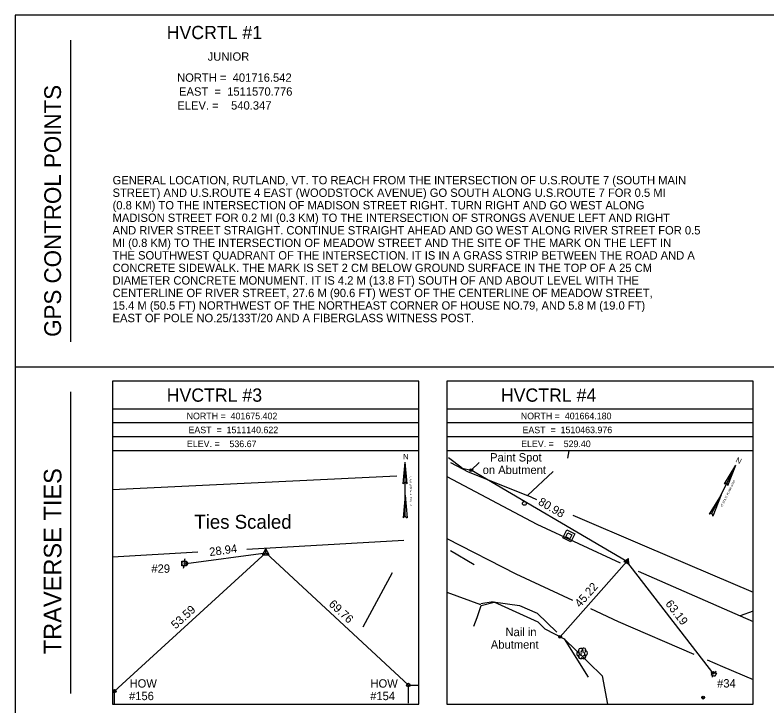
# Model space of a CAD drawing. Extents: x 1508412 to 1509054, y 401108 to 401963.
# Drawn here: x 1508413.7 to 1508683.7, y 401715.1 to 401963.2 of the extents above; entities that cross this region are included whole.
import ezdxf

# ---------------------------------------------------------------- set-up
doc = ezdxf.new("R2010")
doc.units = 0
for name, color, linetype in [('BSUBM', 7, 'Continuous'), ('CBP', 7, 'Continuous'), ('CPSM', 7, 'Continuous'), ('Default', 7, 'Continuous'), ('DS', 7, 'Continuous'), ('LAWA', 7, 'Continuous'), ('LBC', 7, 'Continuous'), ('Level 3', 7, 'Continuous'), ('Level 5', 7, 'Continuous'), ('LFNC', 7, 'Continuous'), ('LTD', 7, 'Continuous'), ('LWS', 7, 'Continuous'), ('NBL2', 7, 'Continuous'), ('NNA_P', 7, 'Continuous'), ('PET', 7, 'Continuous'), ('RDP', 7, 'Continuous'), ('RGR', 7, 'Continuous'), ('SSGN', 7, 'Continuous'), ('UP', 7, 'Continuous'), ('UPGW', 7, 'Continuous')]:
    doc.layers.add(name, color=color, linetype=linetype)

msp = doc.modelspace()

# ---------------------------------------------------------------- linework, layer by layer
at = {"layer": 'BSUBM'}
for p, q in [((1508574.2, 401800.46), (1508577.53, 401799.76)), ((1508577.53, 401799.76), (1508580.38, 401802.47)), ((1508603.93, 401742.74), (1508610.85, 401739.18)), ((1508610.85, 401739.18), (1508619.53, 401725.38))]:
    msp.add_line(p, q, dxfattribs=at)
for points in [[(1508574.2, 401800.46), (1508569.35, 401804.23)], [(1508601.58, 401745.15), (1508585.76, 401752.32)], [(1508601.58, 401745.15), (1508603.93, 401742.74)]]:
    msp.add_lwpolyline(points, dxfattribs=at)
at = {"layer": 'CBP'}
for centre, radius in [((1508577.53, 401799.76), 0.5), ((1508577.53, 401799.76), 0.0667), ((1508475.09, 401766.23), 0.625), ((1508475.09, 401766.23), 0.0833), ((1508609.46, 401739.9), 0.5), ((1508609.46, 401739.9), 0.0667), ((1508664.25, 401726.94), 0.5), ((1508664.25, 401726.94), 0.0667), ((1508554.92, 401722.59), 0.625), ((1508554.92, 401722.59), 0.0833), ((1508449.38, 401720.4), 0.625), ((1508449.38, 401720.4), 0.625), ((1508449.38, 401720.4), 0.0833), ((1508449.38, 401720.4), 0.0833)]:
    msp.add_circle(centre, radius, dxfattribs=at)
at = {"layer": 'CPSM'}
for p, q in [((1508502.5, 401769.29), (1508503.75, 401771.46)), ((1508505, 401769.29), (1508503.75, 401771.46)), ((1508503.75, 401770.02), (1508503.75, 401771.46)), ((1508502.5, 401769.29), (1508503.75, 401770.02)), ((1508502.5, 401769.29), (1508505, 401769.29)), ((1508503.75, 401770.02), (1508503.75, 401770.02)), ((1508503.75, 401770.02), (1508505, 401769.29)), ((1508632.27, 401766.93), (1508633.93, 401768.04)), ((1508633.42, 401767), (1508633.93, 401768.04)), ((1508634.06, 401766.04), (1508633.93, 401768.04)), ((1508632.27, 401766.93), (1508633.42, 401767)), ((1508632.27, 401766.93), (1508634.06, 401766.04)), ((1508633.42, 401767), (1508633.42, 401767)), ((1508633.42, 401767), (1508634.06, 401766.04))]:
    msp.add_line(p, q, dxfattribs=at)
at = {"layer": 'Default'}
for p, q in [((1508633.42, 401767), (1508577.53, 401799.76)), ((1508503.75, 401770.02), (1508449.38, 401720.4)), ((1508475.09, 401766.23), (1508503.75, 401770.02)), ((1508554.92, 401722.59), (1508503.75, 401770.02)), ((1508633.42, 401767), (1508609.46, 401739.9)), ((1508664.25, 401726.94), (1508633.42, 401767))]:
    msp.add_line(p, q, dxfattribs=at)
at = {"layer": 'DS'}
for p, q in [((1508610.43, 401775.44), (1508611.85, 401778.31)), ((1508611.85, 401778.31), (1508614.72, 401776.89)), ((1508611.5, 401775.8), (1508612.21, 401777.23)), ((1508612.94, 401775.09), (1508611.5, 401775.8)), ((1508612.21, 401777.23), (1508613.65, 401776.53)), ((1508612.58, 401776.16), (1508612.58, 401776.16)), ((1508612.58, 401776.16), (1508612.58, 401776.16)), ((1508613.65, 401776.53), (1508612.94, 401775.09)), ((1508614.72, 401776.89), (1508613.3, 401774.02)), ((1508613.3, 401774.02), (1508610.43, 401775.44))]:
    msp.add_line(p, q, dxfattribs=at)
at = {"layer": 'LAWA'}
for points in [[(1508612.19, 401804.06), (1508612.65, 401806.71)], [(1508570.07, 401802.5), (1508576.44, 401799.14)], [(1508576.44, 401799.14), (1508597.68, 401790.66)], [(1508597.68, 401790.66), (1508606.93, 401799.21)], [(1508549.06, 401762.88), (1508538.62, 401743.39)], [(1508568.69, 401755.89), (1508580.89, 401751.55)], [(1508585.42, 401752.42), (1508581.01, 401751.72)], [(1508585.42, 401752.42), (1508594.85, 401751.13)], [(1508594.85, 401751.13), (1508601.19, 401748.35), (1508608.27, 401741.58)], [(1508611.32, 401738.67), (1508614.67, 401735.47), (1508624.56, 401725.85), (1508626.4, 401715.71)]]:
    msp.add_lwpolyline(points, dxfattribs=at)
at = {"layer": 'LBC'}
for points in [[(1508554.92, 401716.01), (1508554.92, 401722.59), (1508558.42, 401722.59)], [(1508449.38, 401715.71), (1508449.38, 401720.4), (1508448.69, 401720.4)]]:
    msp.add_lwpolyline(points, dxfattribs=at)
at = {"layer": 'LFNC'}
for points in [[(1508601.1, 401789.1), (1508597.68, 401790.66)], [(1508613.97, 401783.53), (1508639.76, 401772.58), (1508678.69, 401755.98)]]:
    msp.add_lwpolyline(points, dxfattribs=at)
at = {"layer": 'LTD'}
msp.add_line((1508617.33, 401733.99), (1508617.33, 401733.99), dxfattribs=at)
msp.add_line((1508617.33, 401733.99), (1508617.33, 401733.99), dxfattribs=at)
msp.add_arc((1508617.87, 401735.01), 0.838, 309.2777, 154.7068, dxfattribs=at)
for centre, major_axis, ratio, start_param, end_param in [((1508617, 401734.75), (0.687, -0.795), 0.895232, 1.570796, 4.712389), ((1508616.3, 401733.87), (0.05, -0.954), 0.959034, 3.141593, 6.283185), ((1508616.8, 401732.92), (0.565, 0.667), 0.942809, 1.570796, 4.712389), ((1508616.74, 401733.62), (-0.478, 0.161), 0.423636, 0, 3.141593), ((1508617.35, 401734.4), (-0.43, -0.494), 0.645439, 3.141593, 6.283185), ((1508617.76, 401733.04), (-0.501, 0.954), 0.841452, 1.570796, 4.712389), ((1508617.63, 401733.7), (-0.123, 0.655), 0.989748, 3.141593, 6.283185), ((1508618.29, 401734.04), (-0.989, 0.057), 0.949671, 1.570796, 4.712389)]:
    msp.add_ellipse(centre, major_axis=major_axis, ratio=ratio, start_param=start_param, end_param=end_param, dxfattribs=at)
at = {"layer": 'LWS'}
msp.add_lwpolyline([(1508578.46, 401743.72), (1508579.67, 401746.83), (1508581.03, 401751.18), (1508585.76, 401752.32)], dxfattribs=at)
at = {"layer": 'NBL2'}
for p, q in [((1508433.7, 401845.87), (1508433.7, 401954.21)), ((1508413.7, 401836.87), (1509053.7, 401836.87)), ((1508433.7, 401719.54), (1508433.7, 401827.87)), ((1508558.69, 401821.71), (1508448.69, 401821.71)), ((1508678.69, 401821.71), (1508568.69, 401821.71)), ((1508558.69, 401816.71), (1508448.69, 401816.71)), ((1508678.69, 401816.71), (1508568.69, 401816.71)), ((1508558.69, 401811.71), (1508448.69, 401811.71)), ((1508678.69, 401811.71), (1508568.69, 401811.71)), ((1508558.69, 401806.71), (1508448.69, 401806.71)), ((1508678.69, 401806.71), (1508568.69, 401806.71))]:
    msp.add_line(p, q, dxfattribs=at)
for points in [[(1508413.7, 401543.21), (1509053.7, 401543.21), (1509053.7, 401963.21), (1508413.7, 401963.21)], [(1508448.69, 401715.71), (1508558.69, 401715.71), (1508558.69, 401831.71), (1508448.69, 401831.71)], [(1508568.69, 401715.71), (1508678.69, 401715.71), (1508678.69, 401831.71), (1508568.69, 401831.71)]]:
    msp.add_lwpolyline(points, close=True, dxfattribs=at)
at = {"layer": 'NNA_P'}
for p, q in [((1508553.11, 401794.8), (1508553.81, 401802.59)), ((1508553.81, 401783.22), (1508553.81, 401802.59)), ((1508554.5, 401794.8), (1508553.81, 401802.59)), ((1508663.91, 401784.15), (1508672.47, 401801.52)), ((1508668.41, 401794.84), (1508672.47, 401801.52)), ((1508669.65, 401794.23), (1508672.47, 401801.52)), ((1508553.11, 401794.8), (1508553.81, 401795.56)), ((1508554.5, 401794.8), (1508553.81, 401795.56)), ((1508668.41, 401794.84), (1508669.37, 401795.22)), ((1508669.65, 401794.23), (1508669.37, 401795.22)), ((1508553.81, 401790.74), (1508553.09, 401782.58)), ((1508553.81, 401790.74), (1508554.53, 401782.58)), ((1508667.24, 401790.9), (1508662.98, 401783.89)), ((1508667.24, 401790.9), (1508664.27, 401783.26)), ((1508663.91, 401784.15), (1508662.98, 401783.89)), ((1508663.91, 401784.15), (1508664.27, 401783.26)), ((1508553.81, 401783.21), (1508553.09, 401782.58)), ((1508553.81, 401783.21), (1508554.53, 401782.58))]:
    msp.add_line(p, q, dxfattribs=at)
at = {"layer": 'PET'}
for p, q in [((1508448.69, 401792.81), (1508550.83, 401797.67)), ((1508496.9, 401771.38), (1508553.3, 401774.6)), ((1508448.69, 401768.63), (1508479.37, 401770.38))]:
    msp.add_line(p, q, dxfattribs=at)
for points in [[(1508568.69, 401797.48), (1508601.12, 401780.4), (1508630.94, 401766.49)], [(1508568.69, 401775.21), (1508593.51, 401762.47), (1508613.83, 401753.05)], [(1508637.44, 401763.46), (1508674.05, 401747.45), (1508678.69, 401745.42)], [(1508620.3, 401750.05), (1508630.22, 401745.45), (1508657.39, 401733.71)], [(1508662.27, 401731.6), (1508667.67, 401729.26), (1508678.69, 401724.58)]]:
    msp.add_lwpolyline(points, dxfattribs=at)
at = {"layer": 'RDP'}
msp.add_lwpolyline([(1508678.69, 401749.15), (1508674.05, 401747.45)], dxfattribs=at)
at = {"layer": 'RGR'}
msp.add_lwpolyline([(1508570.02, 401770.86), (1508578.61, 401765.85)], dxfattribs=at)
at = {"layer": 'SSGN'}
for p, q in [((1508595.69, 401788.97), (1508598.08, 401787.79)), ((1508596.58, 401787.79), (1508596.58, 401787.79))]:
    msp.add_line(p, q, dxfattribs=at)
msp.add_circle((1508596.58, 401787.79), 0.667, dxfattribs=at)
at = {"layer": 'UP'}
for p, q in [((1508474.72, 401767.9), (1508474.47, 401767.07)), ((1508473.63, 401765.4), (1508473.63, 401767.07)), ((1508473.63, 401767.07), (1508475.3, 401767.07)), ((1508475.3, 401765.4), (1508473.63, 401765.4)), ((1508474.22, 401764.57), (1508474.47, 401765.4)), ((1508474.47, 401766.23), (1508474.47, 401766.23)), ((1508475.3, 401767.07), (1508475.3, 401765.4)), ((1508663.79, 401726.18), (1508664.38, 401727.38)), ((1508664.38, 401727.38), (1508665.58, 401726.79)), ((1508665.45, 401727.59), (1508664.98, 401727.08)), ((1508664.99, 401725.59), (1508663.79, 401726.18)), ((1508663.92, 401725.38), (1508664.39, 401725.88)), ((1508664.68, 401726.48), (1508664.68, 401726.48)), ((1508665.58, 401726.79), (1508664.99, 401725.59))]:
    msp.add_line(p, q, dxfattribs=at)
for centre, radius in [((1508474.47, 401766.23), 0.833), ((1508664.68, 401726.48), 0.667)]:
    msp.add_circle(centre, radius, dxfattribs=at)
at = {"layer": 'UPGW'}
for radius in [0.5, 0.0667]:
    msp.add_circle((1508660.75, 401718.05), radius, dxfattribs=at)

# ---------------------------------------------------------------- texts
at = {"layer": 'Default'}
for s, p in [('GENERAL LOCATION, RUTLAND, VT. TO REACH FROM THE INTERSECTION OF U.S.ROUTE 7 (SOUTH MAIN ', (1508448.72, 401902.4)), ('STREET) AND U.S.ROUTE 4 EAST (WOODSTOCK AVENUE) GO SOUTH ALONG U.S.ROUTE 7 FOR 0.5 MI ', (1508448.72, 401897.9)), ('(0.8 KM) TO THE INTERSECTION OF MADISON STREET RIGHT. TURN RIGHT AND GO WEST ALONG ', (1508448.72, 401893.4)), ('MADISON STREET FOR 0.2 MI (0.3 KM) TO THE INTERSECTION OF STRONGS AVENUE LEFT AND RIGHT ', (1508448.72, 401888.9)), ('AND RIVER STREET STRAIGHT. CONTINUE STRAIGHT AHEAD AND GO WEST ALONG RIVER STREET FOR 0.5 ', (1508448.72, 401884.4)), ('MI (0.8 KM) TO THE INTERSECTION OF MEADOW STREET AND THE SITE OF THE MARK ON THE LEFT IN ', (1508448.72, 401879.9)), ('THE SOUTHWEST QUADRANT OF THE INTERSECTION. IT IS IN A GRASS STRIP BETWEEN THE ROAD AND A ', (1508448.72, 401875.4)), ('CONCRETE SIDEWALK. THE MARK IS SET 2 CM BELOW GROUND SURFACE IN THE TOP OF A 25 CM ', (1508448.72, 401870.9)), ('DIAMETER CONCRETE MONUMENT. IT IS 4.2 M (13.8 FT) SOUTH OF AND ABOUT LEVEL WITH THE ', (1508448.72, 401866.4)), ('CENTERLINE OF RIVER STREET, 27.6 M (90.6 FT) WEST OF THE CENTERLINE OF MEADOW STREET, ', (1508448.72, 401861.9)), ('15.4 M (50.5 FT) NORTHWEST OF THE NORTHEAST CORNER OF HOUSE NO.79, AND 5.8 M (19.0 FT) ', (1508448.72, 401857.4)), ('EAST OF POLE NO.25/133T/20 AND A FIBERGLASS WITNESS POST. ', (1508448.72, 401852.9))]:
    msp.add_text(s, height=3, dxfattribs=at).set_placement(p)
at = {"layer": 'Level 3'}
for s, p in [('Paint Spot', (1508584.28, 401802.86)), ('on Abutment', (1508581.61, 401798.36)), ('#29', (1508462.66, 401762.9)), ('Nail in', (1508589.81, 401740.13)), ('Abutment', (1508584.54, 401735.63)), ('HOW', (1508454.83, 401721.65)), ('HOW', (1508541.33, 401721.65)), ('#34', (1508665.8, 401721.69)), ('#156', (1508454.63, 401717.15)), ('#154', (1508541.22, 401717.15))]:
    msp.add_text(s, height=3, dxfattribs=at).set_placement(p)
for s, rotation, p in [('80.98', 329.6259, (1508601.28, 401787.57)), ('28.94', 7.517, (1508483.65, 401768.88)), ('45.22', 48.5176, (1508616.59, 401750.23)), ('69.76', 317.1763, (1508526.12, 401751.33)), ('63.19', 307.5795, (1508647.06, 401751.73)), ('53.59', 42.3794, (1508471.39, 401742.52))]:
    msp.add_text(s, height=3, rotation=rotation, dxfattribs=at).set_placement(p)
at = {"layer": 'Level 5'}
msp.add_text('Ties Scaled', height=5, dxfattribs=at).set_placement((1508478.08, 401778.71))
at = {"layer": 'NBL2'}
for s, height, p in [('     HVCRTL #1     ', 4.75, (1508459.34, 401954.56)), ('   JUNIOR   ', 3, (1508479.53, 401946.8)), ('NORTH =  401716.542 ', 3, (1508471.88, 401939.24)), ('EAST  =  1511570.776', 3, (1508472.59, 401934.24)), ('ELEV. =    540.347  ', 3, (1508471.99, 401929.24)), ('     HVCTRL #3     ', 4.75, (1508459.34, 401824.33)), ('     HVCTRL #4     ', 4.75, (1508579.34, 401824.33)), ('NORTH =  401675.402 ', 2.375, (1508475.31, 401818.02)), ('NORTH =  401664.180 ', 2.375, (1508595.31, 401818.02)), ('EAST  =  1511140.622', 2.375, (1508475.97, 401813.02)), ('EAST  =  1510463.976', 2.375, (1508595.9, 401813.02)), ('ELEV. =    536.67   ', 2.375, (1508475.42, 401808.02)), ('ELEV. =    529.40   ', 2.375, (1508595.42, 401808.02))]:
    msp.add_text(s, height=height, dxfattribs=at).set_placement(p)
for s, height, p in [('GPS CONTROL POINTS', 6, (1508430.2, 401847.62)), ('TRAVERSE TIES', 6.3332, (1508430.36, 401733.64))]:
    msp.add_text(s, height=height, rotation=90, dxfattribs=at).set_placement(p)
at = {"layer": 'NNA_P'}
msp.add_text('N', height=1.97, dxfattribs=at).set_placement((1508553.04, 401803.6))
for s, height, rotation, p in [('N', 1.97, 333.7505, (1508672.24, 401802.77)), ('VT STATE PLANE GRID', 0.7, 90.0204, (1508556.16, 401786.78)), ('VT STATE PLANE GRID', 0.7, 63.7709, (1508667.59, 401786.3))]:
    msp.add_text(s, height=height, rotation=rotation, dxfattribs=at).set_placement(p)

doc.saveas('drawing.dxf')
